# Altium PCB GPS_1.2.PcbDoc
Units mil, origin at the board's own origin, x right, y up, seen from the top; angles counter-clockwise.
Board outline 1968.5 x 2139.68 mil, 4 copper layers (Top Layer, GND, VDD, Bottom Layer); 63 components, 51 nets, 275 pads, 131 vias.
Unrouted connection lines stored in the file: 5.
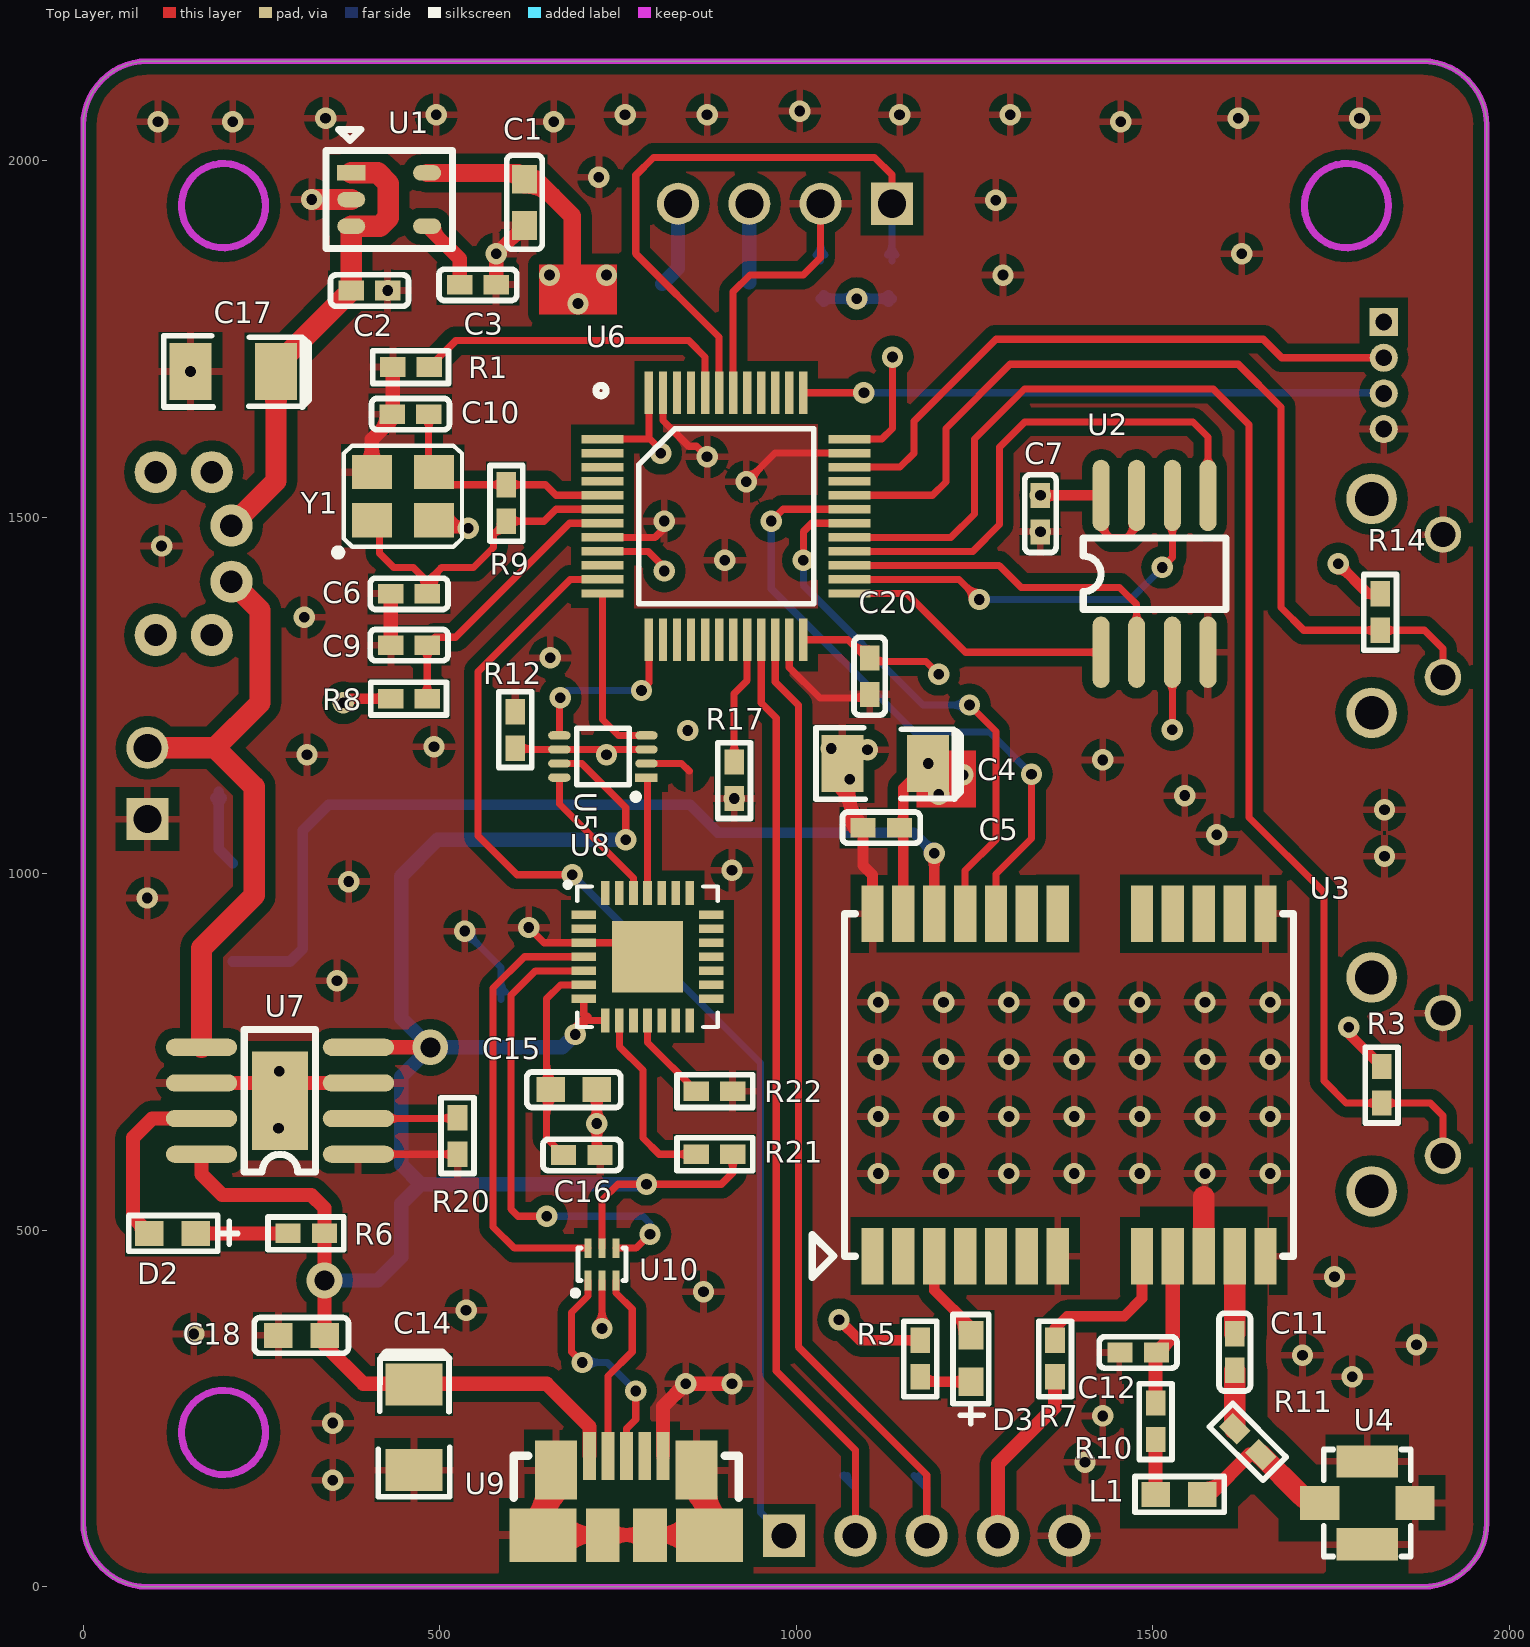
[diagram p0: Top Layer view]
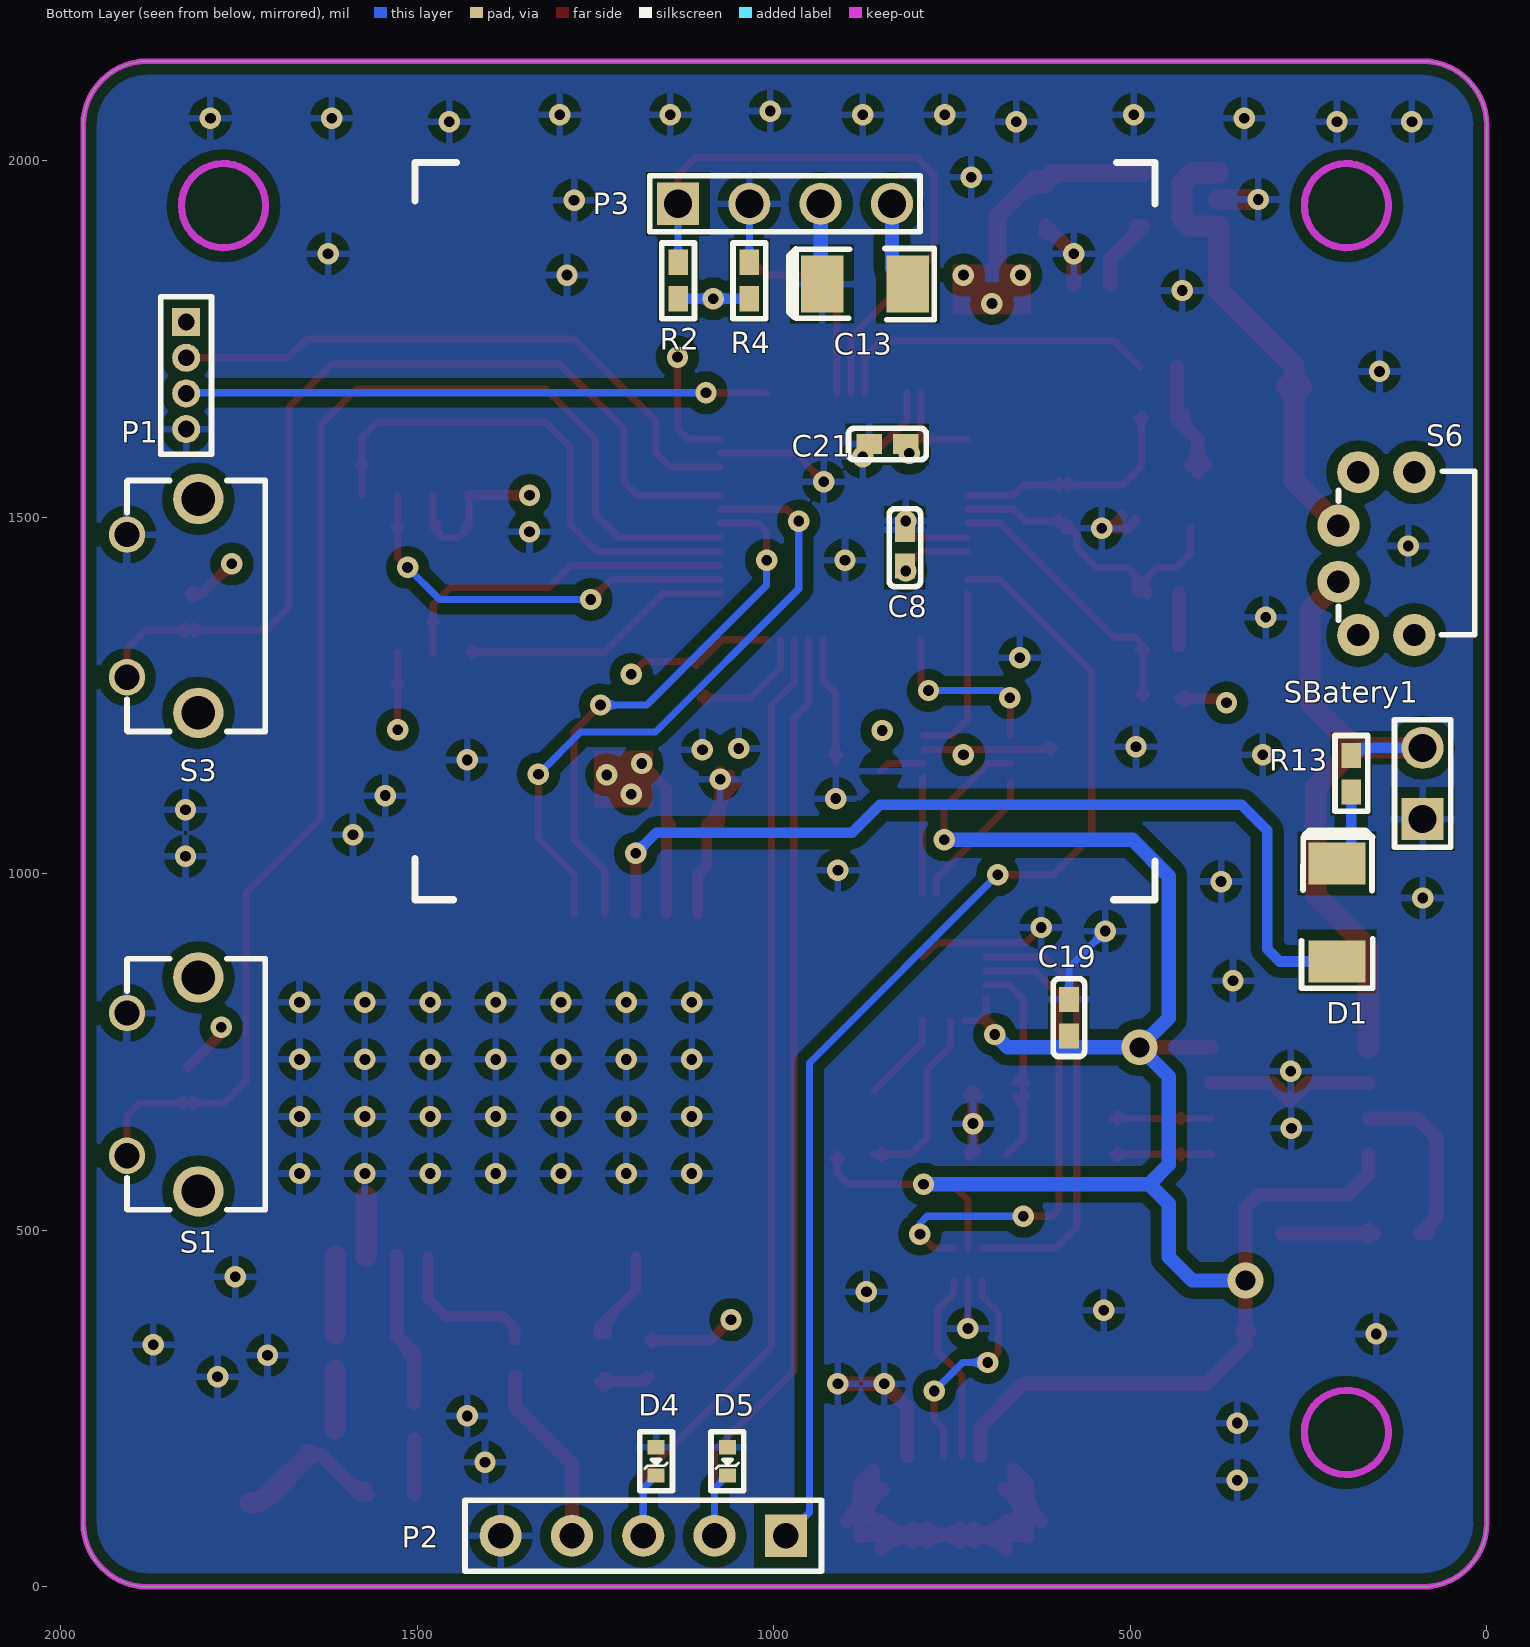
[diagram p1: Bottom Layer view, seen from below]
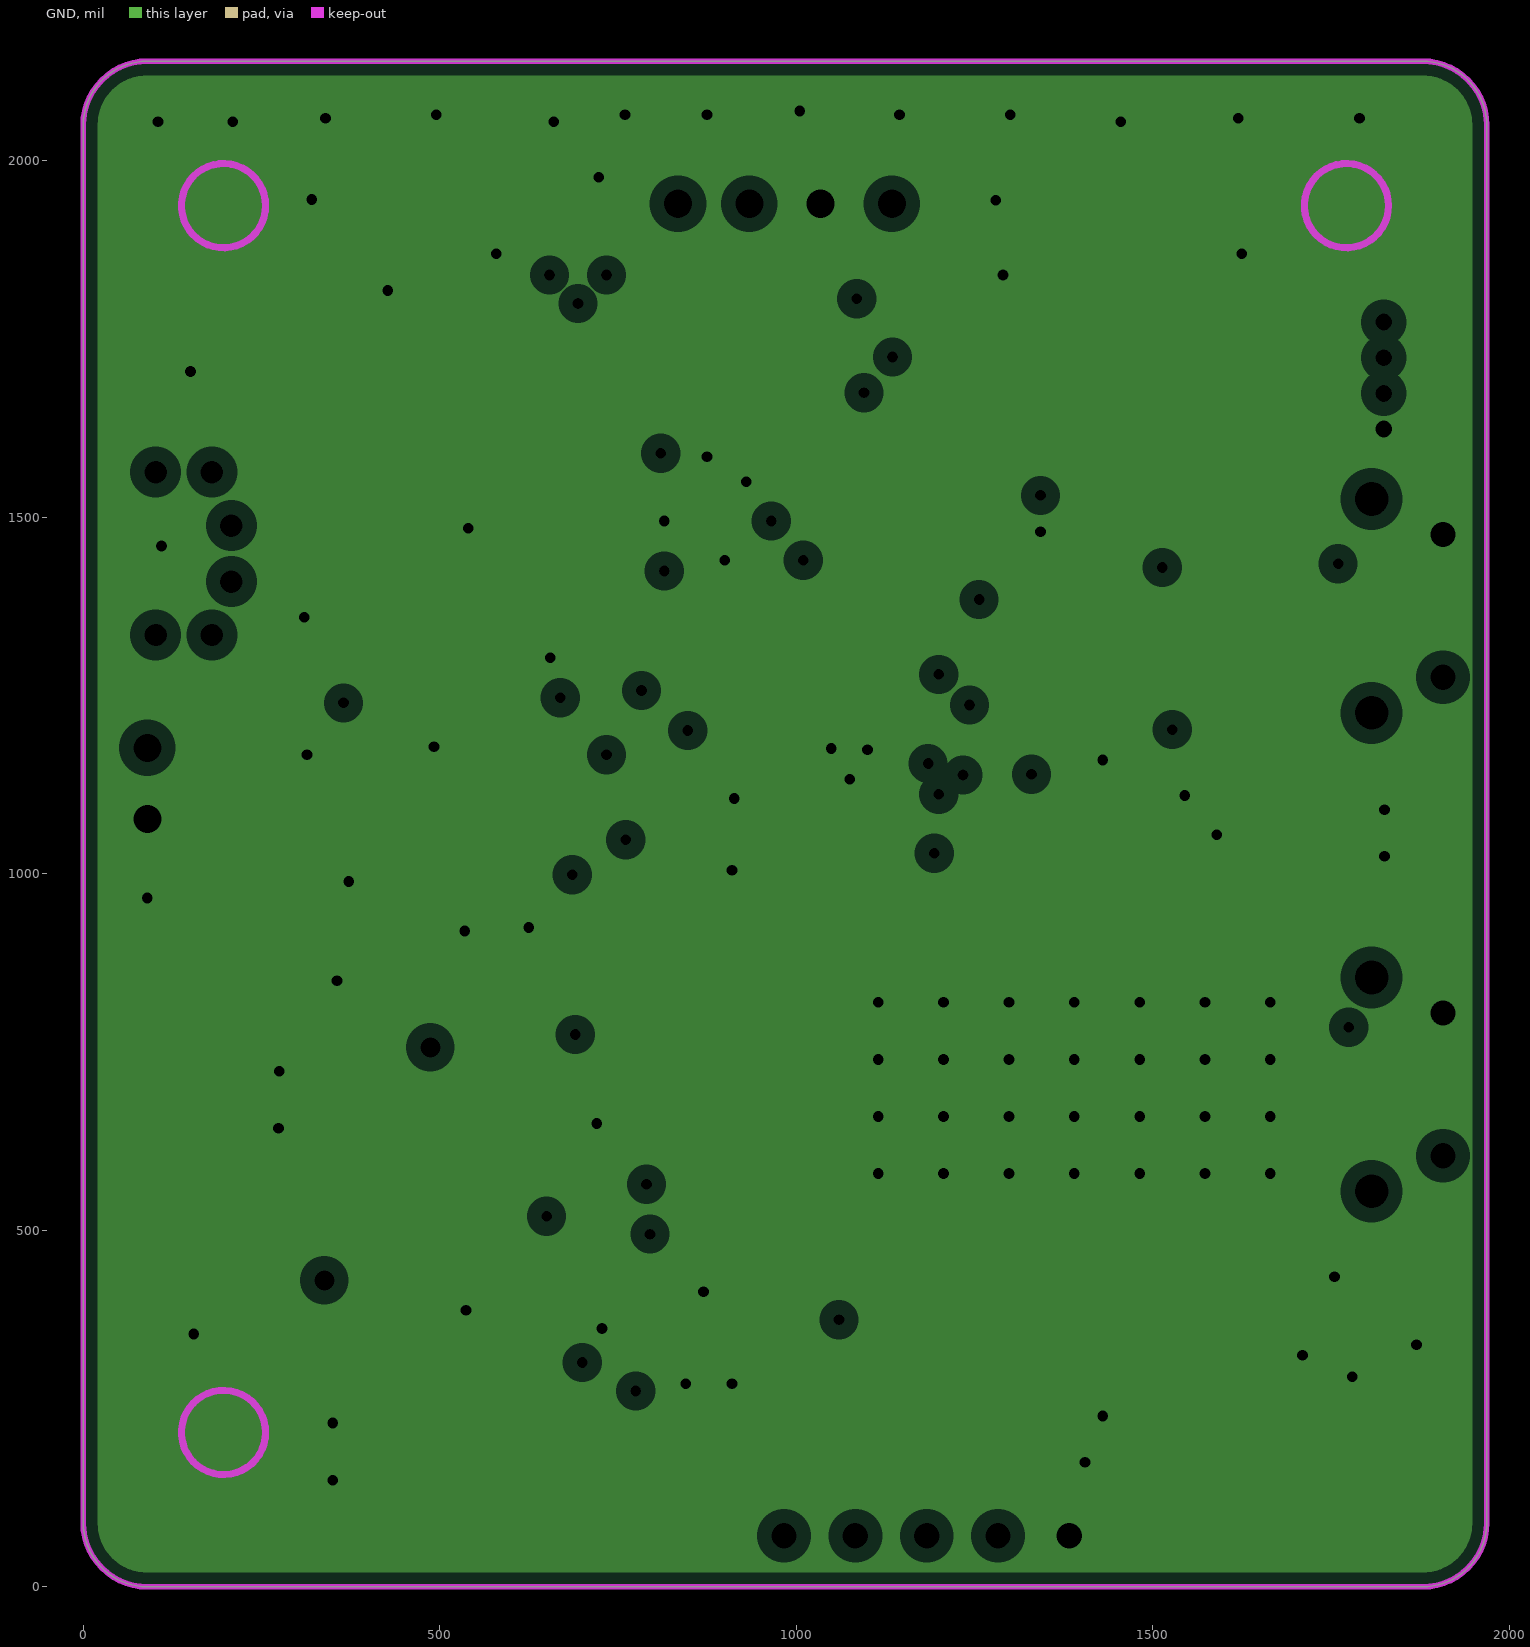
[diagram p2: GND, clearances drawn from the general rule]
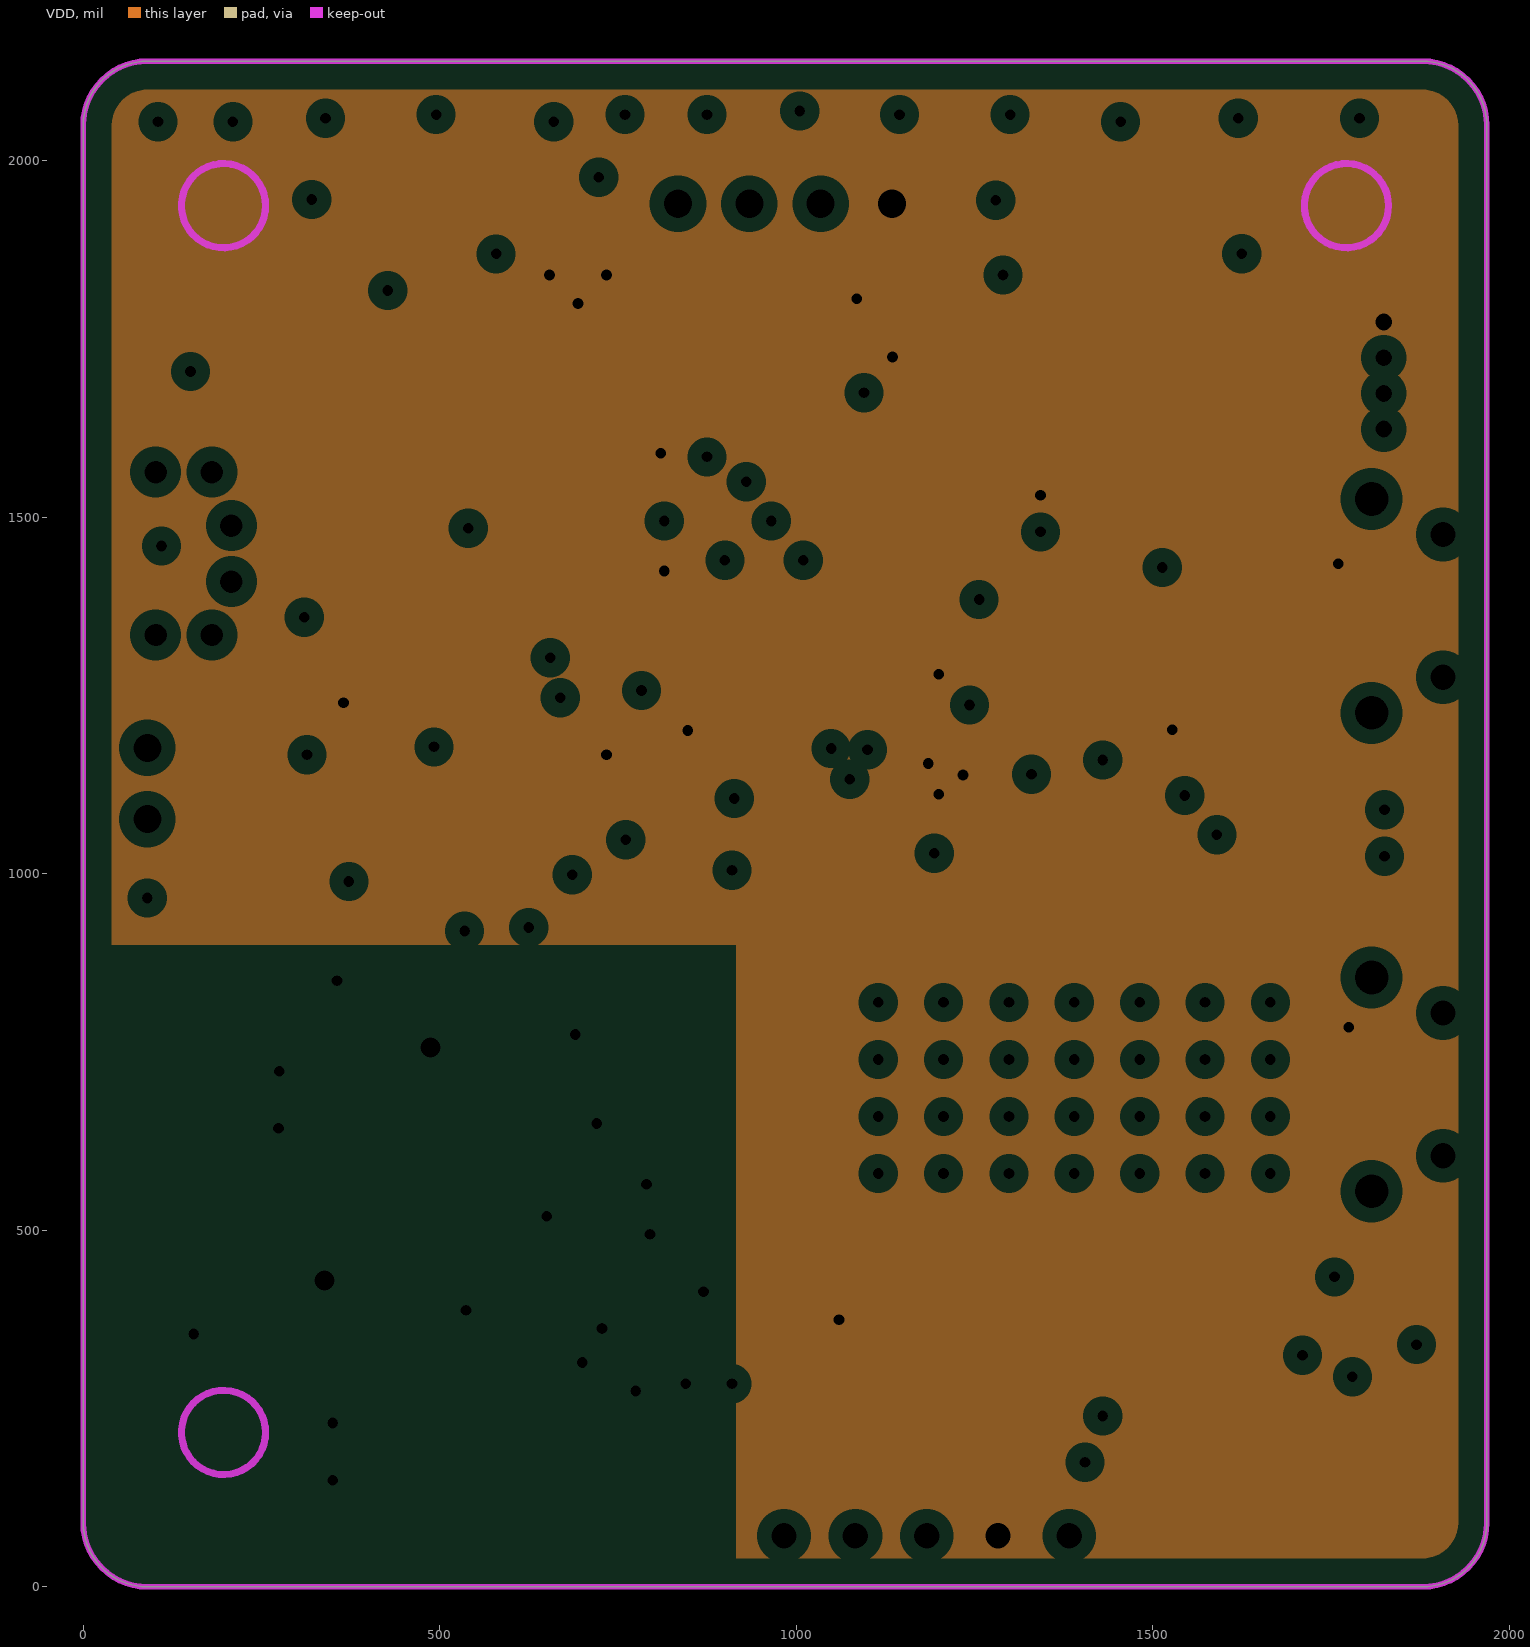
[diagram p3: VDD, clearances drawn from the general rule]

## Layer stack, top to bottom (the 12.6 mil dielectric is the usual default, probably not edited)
Top Layer: signal copper 1.4
Dielectric: core 12.6, FR-4, Dk 4.8
GND: plane copper 1.4, net GND
Dielectric: prepreg 12.6, FR-4, Dk 4.8
VDD: plane copper 1.4, net VDD
Dielectric: core 12.6, FR-4, Dk 4.8
Bottom Layer: signal copper 1.4

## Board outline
0,2049.68 0,90 ccw(c90,90) 90,0 1878.5,0 ccw(c1878.5,90) 1968.5,90 1968.5,2049.68 ccw(c1878.5,2049.68) 1878.5,2139.68 90,2139.68 ccw(c90,2049.68) 0,2049.68

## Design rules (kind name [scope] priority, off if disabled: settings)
Clearance Clearance_RF [InNetClass('RF')] p1: gap=30
Clearance [All] p2: gap=10
DiffPairsRouting [All] p1: maxlimit=10 minlimit=10 mostfreqgap=10 maxuncoupledlength=500
HoleSize [All] p1 off: absolutevalues=TRUE maxlimit=100 minlimit=1 maxpercent=80.000 minpercent=20.000
HoleToHoleClearance [All] p1 off: gap=10 allowstackedmicrovias=TRUE
LayerPairs [All] p1 off: enforce=TRUE
MinimumSolderMaskSliver [All] p1 off: minsoldermaskwidth=10
NetAntennae [All] p1 off: netantennaetolerance=0
PlaneClearance [All] p1: clearance=20
PlaneConnect [All] p1: planeconnectstyle=Relief reliefexpansion=20 reliefentries=4 reliefconductorwidth=10 reliefairgap=10
PolygonConnect [All] p1: connectstyle=Relief reliefconductorwidth=10 reliefentries=4 polygonreliefangle="90 Angle"
RoutingVias [All] p1: holewidth=28 width=50 viastyle="Through Hole" minholewidth=0 minwidth=0 maxholewidth=28 maxwidth=50
SilkToSilkClearance [All] p1 off: silktosilkclearance=10
SilkscreenOverComponentPads [All] p1 off: minsilkscreentomaskgap=10
SolderMaskExpansion [All] p1: expansion=4
Width [All] p1: maxlimit=50 minlimit=10 preferedwidth=10
18 further rules are at their usual default settings.

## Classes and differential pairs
net class RF: NetC11_1 NetL1_1 NetL1_2 RF_IN RF_VCC
differential pair D: +D_P -D_N

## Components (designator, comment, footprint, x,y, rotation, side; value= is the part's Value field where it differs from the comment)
C1 "10uF/10V" C0603 619,1941.68 r90 top
C2 "0.1uF/10V" C0402 376,1818 r180 top
C3 "0.01uF/10V" C0402 528,1826 r180 top
C4 "10uF/10V" 3528 1185,1154.68 r180 top
C5 "0.1uF/10V" C0402 1145,1064.68 r0 top
C6 "18pF/10V" C0402 431.5,1392.68 r180 top
C7 "0.01uF/10V" C0402 1342.5,1530.68 r90 top
C8 "0.01uF/10V" C0402 816,1431.68 r270 bottom
C9 "0.01uF/10V" C0402 431.5,1320.68 r180 top
C10 "18pF/10V" C0402 433.5,1644.68 r180 top
C11 "470pF" C0402 1615,303.68 r270 top
C12 "33nF" C0402 1454,328.68 r180 top
C13 "10uF/10V" C1206 872,1827 r180 bottom
C14 "10uF/10V" 3528 464,283.68 r270 top
C15 "4.7uF/10V" C0603 688,697.18 r180 top
C16 "0.1uF/10V" C0402 673.82,605.68 r180 top
C17 "10uF/10V" 3528 270.49,1704.53 r180 top
C18 "10uF/10V" C0603 306,352.68 r180 top
C19 "0.1uF/10V" C0402 586,772.68 r270 bottom
C20 "0.01uF/10V" C0402 1103,1302.68 r90 top
C21 "0.01uF/10V" C0402 815,1602.68 r180 bottom
D1 "IN4148" L1206 210,1014.68 r270 bottom
D2 "LED0" LED0603 158,495.68 r180 top
D3 "LED0" LED0603 1245,287.68 r90 top
D4 "PESD0402-140" 0402-TVS 1167,143.68 r270 bottom
D5 "PESD0402-140" 0402-TVS 1067,143.68 r270 bottom
L1 "6.8nH" R0603 1537,129.68 r180 top
P1 "MHDR1X4" SIP4_1.27 1824,1773.68 r0 bottom
P2 "Header 5" HDR1X5 983,71.68 r0 bottom
P3 "MHDR1X4" OLED 984.25,1939.68 r180 bottom locked
R1 "10K/5%" R0402 485.5,1710.68 r0 top
R2 "5.1K/5%" R0402 1134,1857.68 r90 bottom
R3 "10K/5%" R0402 1821,729.68 r90 top
R4 "5.1K/5%" R0402 1034.25,1857.68 r90 bottom
R5 "510R/5%" R0402 1174,345.68 r90 top
R6 "1K/5%" R0402 338.46,495.68 r0 top
R7 "10K/5%" R0402 1363,345.68 r90 top
R8 "10K/5%" R0402 482.5,1245.68 r0 top
R9 "1M/5%" R0402 593.5,1545.68 r90 top
R10 "10R/5%" R0402 1504,257.68 r90 top
R11 "0R/5%" R0402 1615,221.68 r135 top
R12 "10K/5%" R0402 606,1176 r270 top
R13 "105K/5%" R0402 190,1114.68 r270 bottom
R14 "10K/5%" R0402 1819,1392.68 r90 top
R17 "10K/5%" R0402 913,1156.68 r90 top
R20 "2K/5%" R0402 525,606.68 r270 top
R21 "1K/5%" R0402 859.82,606.68 r180 top
R22 "10K/5%" R0402 859.82,695.18 r180 top
S1 "SW-PB" KEY2 1907,704.68 r270 bottom
S3 "SW-PB" KEY2 1907,1375.68 r270 bottom
S6 "SW-PB" KEY1 208,1488.43 r270 bottom
SBatery1 "SBatery" SIP2 90,1076.68 r90 bottom
U1 "TPS73633DBVR" SOP5-TPS73633DBVR 376,1983 r0 top
U2 "FM25V01" SO-8 1427.5,1310.68 r90 top
U3 "NEO-M8N" NEO-M8N 1107,463.68 r0 top
U4 "antenna" "Active antenna" 1801,117.68 r180 top
U5 "TXS0102" R-PDSO-G8 790,1135 r180 top
U6 "STM32F10xC8T6" LQFP-48 728.5,1609.68 r0 top
U7 "TP4056" SO-8-1 276,681.68 r180 top
U8 "CP2102" QFN-28 702,942.68 r0 top
U9 "USB" MOLEX-47346-0001 710,183.68 r0 top
U10 "NUF2042XV6T1" UDFN 708,429.68 r0 top
Y1 "16MHz" OSCILLATOR-3.2X2.5 448.5,1529.68 r90 top

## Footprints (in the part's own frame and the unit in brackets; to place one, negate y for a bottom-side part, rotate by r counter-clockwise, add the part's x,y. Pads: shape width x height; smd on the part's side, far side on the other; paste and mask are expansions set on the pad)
0402-TVS [mil]
  rect 20x24 smd: 1(-52,2) 2(-12.31,2)
  silkscreen extent -74,-21 9,25
3528 [mil]
  rect 59.05x80 smd: 1(0,0) 2(120,0)
  silkscreen extent -46,-50 157,50
"Active antenna" [mm]
  rect 1.4x1.2 smd: 0(-1.7,0) 1(1.7,0)
  rect 2.2x1.15 smd: 0(0,1.475) 0(0,-1.475)
  silkscreen extent -1.55,-1.91 1.55,1.91
C0402 [mm]
  rect 0.9x0.7 smd: 1(0,0) 2(-1.3,0)
  silkscreen extent -2.04,-0.56 0.74,0.56
C0603 [mil]
  rect 40x35 smd: 1(-32.5,0) 2(32.5,0)
  silkscreen extent -66,-25 66,25
C1206 [mil]
  rect 59.05x80 smd: 1(-60,0) 2(60,0)
  silkscreen extent -106,-50 97,50
HDR1X5 [mm] "Connector; Header; 5 Position"
  rect 1.5x1.5 hole 0.9: 1(0,0)
  round 1.5 hole 0.9: 2(2.54,0) 3(5.08,0) 4(7.62,0) 5(10.16,0)
  silkscreen extent -1.27,-1.27 11.43,1.27
KEY1 [mm]
  round 1.5 hole 0.8: 0(-1.9,0.7) 0(-1.9,2.7) 0(3.9,0.7) 0(3.9,2.7) 1(0,0) 2(2,0)
  silkscreen extent -1.93,0 3.89,4.85
KEY2 [mm]
  round 1.8 hole 1.2: 0(-3.81,2.54) 0(3.81,2.54)
  round 1.3 hole 0.9: 1(-2.54,0) 2(2.54,0)
  silkscreen extent -4.47,0 4.47,4.93
L1206 [mm]
  rect 1.5x2.032 smd: 1(0,0) 2(3.5,0)
  silkscreen extent -1.16,-1.27 4.45,1.27
LED0603 [mil]
  rect 40x35 smd: 1(0,0) 2(65,0)
  silkscreen extent -59,-25 94,25
LQFP-48 [mm]
  rect 1.5x0.3 smd: 1(0,0) 2(0,-0.5) 3(0,-1) 4(0,-1.5) 5(0,-2) 6(0,-2.5) 7(0,-3) 8(0,-3.5) 9(0,-4) 10(0,-4.5) 11(0,-5) 12(0,-5.5) 25(8.8,-5.5) 26(8.8,-5) 27(8.8,-4.5) 28(8.8,-4) 29(8.8,-3.5) 30(8.8,-3) 31(8.8,-2.5) 32(8.8,-2) 33(8.8,-1.5) 34(8.8,-1) 35(8.8,-0.5) 36(8.8,0)
  rect 0.3x1.5 smd: 13(1.65,-7.15) 14(2.15,-7.15) 15(2.65,-7.15) 16(3.15,-7.15) 17(3.65,-7.15) 18(4.15,-7.15) 19(4.65,-7.15) 20(5.15,-7.15) 21(5.65,-7.15) 22(6.15,-7.15) 23(6.65,-7.15) 24(7.15,-7.15) 37(7.15,1.65) 38(6.65,1.65) 39(6.15,1.65) 40(5.65,1.65) 41(5.15,1.65) 42(4.65,1.65) 43(4.15,1.65) 44(3.65,1.65) 45(3.15,1.65) 46(2.65,1.65) 47(2.15,1.65) 48(1.65,1.65)
  silkscreen extent -0.24,-5.86 7.51,1.91
MOLEX-47346-0001 [mil]
  rect 18x67 smd: 1(0,0) 2(26,0) 3(52,0) 4(77.59,0) 5(103.18,0)
  rect 94x75 smd: 6(-65,-111) 9(168.14,-111)
  rect 59x83 smd: 7(-47,-20) 8(150.43,-20)
  rect 47x75 smd: 10(84.97,-111) 11(19,-111)
  silkscreen extent -106,-59 209,0
NEO-M8N [mm]
  rect 0.8x2 smd: 1(0,0) 2(1.1,0) 3(2.2,0) 4(3.3,0) 5(4.4,0) 6(5.5,0) 7(6.6,0) 8(9.6,0) 9(10.7,0) 10(11.8,0) 11(12.9,0) 12(14,0) 13(14,12.2) 14(12.9,12.2) 15(11.8,12.2) 16(10.7,12.2) 17(9.6,12.2) 18(6.6,12.2) 19(5.5,12.2) 20(4.4,12.2) 21(3.3,12.2) 22(2.2,12.2) 23(1.1,12.2) 24(0,12.2)
  silkscreen extent -2.14,-0.76 15,12.2
OLED [mm]
  rect 1.5x1.5 hole 1: 1(-3.81,0)
  round 1.5 hole 1: 2(-1.27,0) 3(1.27,0) 4(3.81,0)
  silkscreen extent -13.18,-24.79 13.18,1.47
OSCILLATOR-3.2X2.5 [mil]
  rect 48x56 smd: 1(-33.73,43.65) 2(-33.73,-43.65) 3(33.73,-43.65) 4(33.73,43.65)
  silkscreen extent -83,-83 71,95
QFN-28 [mil]
  rect 34x12 smd mask+5: 1(0,0) 2(0,-19.68) 3(0,-39.37) 4(0,-59.06) 5(0,-78.74) 6(0,-98.43) 7(0,-118.11) 15(179,-118.11) 16(179,-98.43) 17(179,-78.74) 18(179,-59.06) 19(179,-39.37) 20(179,-19.68) 21(179,0)
  rect 12x34 smd mask+5: 8(30.44,-148.56) 9(50.13,-148.56) 10(69.81,-148.56) 11(89.5,-148.56) 12(109.19,-148.56) 13(128.87,-148.56) 14(148.56,-148.56) 22(148.56,30.44) 23(128.87,30.44) 24(109.19,30.44) 25(89.5,30.44) 26(69.82,30.44) 27(50.13,30.44) 28(30.44,30.44)
  rect 100x100 smd mask+5: 29(89.5,-59.06)
  silkscreen extent -25,-158 188,44
R0402 [mm]
  rect 0.9x0.7 smd: 1(0,0) 2(-1.3,0)
  silkscreen extent -2.01,-0.58 0.69,0.58
R0603 [mil]
  rect 40x35 smd: 1(-32.5,0) 2(32.5,0)
  silkscreen extent -63,-25 62,25
R-PDSO-G8 [mm]
  rect 0.8x0.3 smd: 1(0,0)
  oval 0.8x0.3 smd: 2(0,-0.5) 3(0,-1) 4(0,-1.5) 5(3.1,-1.5) 6(3.1,-1) 7(3.1,-0.5) 8(3.1,0)
  silkscreen extent 0.29,-1.75 2.49,0.78
SIP2 [mm]
  rect 1.5x1.5 hole 1: 1(0,0)
  round 1.5 hole 1: 2(2.54,0)
  silkscreen extent -1,-1 3.54,1
SIP4_1.27 [mm]
  rect 1x1 hole 0.6: 1(0,0)
  round 1 hole 0.6: 2(0,1.27) 3(0,2.54) 4(0,3.81)
  silkscreen extent -0.9,-0.9 0.9,4.71
SO-8 [mil]
  oval 100x24 smd: 1(0,0) 2(0,-50) 3(0,-100) 4(0,-150) 5(220,-150) 6(220,-100) 7(220,-50) 8(220,0)
  silkscreen extent 60,-175 160,25
SO-8-1 [mil]
  rect 78.74x137.8 smd: 0(0,0)
  oval 100x24 smd: 1(-110,75) 2(-110,25) 3(-110,-25) 4(-110,-75) 5(110,-75) 6(110,-25) 7(110,25) 8(110,75)
  silkscreen extent -50,-100 50,100
SOP5-TPS73633DBVR [mm]
  rect 1x0.55 smd: 1(0,0)
  oval 1x0.55 smd: 2(0,-0.95) 3(0,-1.9) 4(2.7,-1.9) 5(2.7,0)
  silkscreen extent -0.9,-2.7 3.6,1.55
UDFN [mm]
  rect 0.25x0.7 smd: 1(0,0) 2(0.5,0) 3(1,0) 4(1,1.15) 5(0.5,1.15) 6(0,1.15)
  silkscreen extent -0.55,-0.55 1.35,1.15

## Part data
C1 C2 C3 C4 C5 C6 C7 C8 C9 C10 C11 C12 C15 C16 C18 C19 C20 C21: library part Cap, "Capacitor"
C13 C14 C17: library part "Cap Pol2", "Polarized Capacitor (Axial)"
D1: library part ZENER2, "Zener Diode"
D2 D3: "Typical INFRARED GaAs LED"
D4 D5: library part "D Zener", "Zener Diode"
L1: library part Inductor, "Inductor"
P1 P3: "Header, 4-Pin"
P2: "Header, 5-Pin"
R1 R2 R3 R4 R5 R6 R7 R8 R9 R10 R11 R12 R13 R14 R17 R20: library part Res2, "Resistor"
R21 R22: library part Resistor, "Resistor SMD - IEC symbol version"
S1 S3 S6: "Switch"
U2: library part FM25CL64B
U6: library part STM32F100C8T6
U8: "Imported"
U9: library part MICRO_USB
Y1: library part XTAL3

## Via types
v1: diameter 30, hole 15, Top Layer to Bottom Layer, 129 vias
v2: diameter 50, hole 28, Top Layer to Bottom Layer, 2 vias

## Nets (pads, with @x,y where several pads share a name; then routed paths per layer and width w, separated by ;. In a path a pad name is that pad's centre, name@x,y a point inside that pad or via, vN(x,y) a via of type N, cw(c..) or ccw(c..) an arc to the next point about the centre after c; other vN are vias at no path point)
BAT: R13.2 S6.2 SBatery1.2 U7.5 | length 979
  Top Layer w30: SBatery1.2 185,1176.68 ; U7.5 166,895.68 240,969.68 240,1121.87 ; S6.2 248,1369.68 248,1239.68 185,1176.68 ; 239.91,1121.78 185,1176.68
  Bottom Layer w15: SBatery1.2 179.18,1176.68 R13.2 ; 158.23,1176.68 cw(c158.23,1138.03) R13.2@185.56,1165.36
D_N: U8.5 U10.4 | length 690.3
  Top Layer w10: v1(650,519.68) 610,519.68 600,529.68 600,829.68 634.26,863.94 U8.5 ; U10.4 775.28,474.96 v1(795,494.68)
  Bottom Layer w10: v1(650,519.68) 785,519.68 795,509.68 v1(795,494.68)
D_P: U8.4 U10.6 | length 625.5
  Top Layer w10: U8.4 618.94,883.63 575,839.68 575,504.68 604.72,474.96 U10.6
FRAM_CLK: U2.6 U6.26 | length 640.1
  Top Layer w10: U6.26 1228.35,1412.84 v1(1256.5,1384.68) ; v1@1246.5,1384.68 ccw(c1222.36,1384.68) 1239.43,1401.76 ccw(c1256.5,1418.83) v1@1256.5,1394.68 ; v1(1513.5,1429.68) 1527.5,1443.69 U2.6 ; U2.6@1522.55,1487.74 cw(c1510.6,1475.79) 1527.5,1475.79 cw(c1544.4,1475.79) U2.6@1532.45,1487.74
  Bottom Layer w10: v1(1256.5,1384.68) 1468.5,1384.68 v1(1513.5,1429.68)
FRAM_CS: U2.1 U6.25 | length 413.2
  Top Layer w10: U6.25 1155.04,1393.15 1237.5,1310.68 U2.1 ; U2.1@1422.55,1305.74 ccw(c1410.6,1293.79) 1410.6,1310.68 ccw(c1410.6,1327.58) U2.1@1422.55,1315.63
FRAM_MISO: U2.2 U6.27 | length 518.8
  Top Layer w10: U6.27 1284.67,1432.52 1315.5,1401.68 1453.5,1401.68 1477.5,1377.68 U2.2 ; U2.2@1472.55,1353.63 ccw(c1460.6,1365.58) 1477.5,1365.58 ccw(c1494.4,1365.58) U2.2@1482.45,1353.63
FRAM_MOSI: U2.5 U6.28 | length 758.5
  Top Layer w10: U6.28 1247.52,1452.2 1285,1489.68 1285,1598.18 1320.5,1633.68 1556.5,1633.68 1577.5,1612.68 U2.5 ; U2.5@1572.55,1573.63 ccw(c1560.6,1585.58) 1577.5,1585.58 ccw(c1594.4,1585.58) U2.5@1582.45,1573.63
GND: C1.1 C2.2 C3.2 C4.2 C5.2 C6.1 C7.2 C8.2 C9.1 C10.1 C12.1 C13.1 C14.2 C15.1 C16.2 C17.2 C18.2 C19.2 C20.2 C21.2 D4.1 D5.1 P1.4 P2.5 P3.2 R1.2 R12.2 R17.2 R20.1 R22.2 S1.1 S3.1 SBatery1.1 U1.2 U2.4 U3.7 U3.10 U3.12 U3.13 U3.24 U4.0 U5.2 U6.8 U6.23 U6.35 U6.47 U7.1 U7.3 U7.6 U8.3 U8.29 U9.5 U9.6 U9.7 U9.8 U9.9 U9.10 U9.11 U10.2 Y1.2 Y1.4 | length 4510.8
  Top Layer w10: U7.1 R20.1 ; U7.1@428.95,601.74 cw(c440.9,589.79) 440.9,606.68 cw(c440.9,623.58) U7.1@428.95,611.63 ; R20.1@518.79,600.48 ccw(c503.8,585.49) 503.8,606.68 ccw(c503.8,627.88) R20.1@518.79,612.89 ; v1(625,924.68) 646.37,903.31 U8.3 771.81,903.31 U8.29 ; v1@720.61,369.44 ccw(c703.54,386.51) 727.69,386.51 ccw(c751.83,386.51) v1@734.76,369.44 ; v1(727.69,362.37) U10.2 ; U6.8 802.2,1471.89 815,1484.68 v1(815,1494.68) ; U5.2 839.31,1154.68 850,1144 ; U6.47 813.15,1635.85 849.31,1599.68 860,1599.68 v1(875,1584.68) ; v1(930,1549.68) 970.31,1590 U6.35 ; v1@930,1559.68 ccw(c930,1583.83) 947.07,1566.76 ccw(c964.14,1549.68) v1@940,1549.68 ; U6.23 990.31,1289.37 1033.18,1246.5 C20.2@1103,1246.5 ; 1079.24,1246.5 ccw(c1079.24,1271.33) C20.2@1096.79,1253.77 ; 1084.37,1246.5 cw(c1084.37,1228.94) C20.2@1096.79,1241.36
  Top Layer w15: Y1.2 503.43,1484.68 v1(540,1484.68) cw(c540,1516.68) Y1.2@511.07,1503 ; C15.1@713.43,690.11 cw(c696.36,673.04) 720.5,673.04 cw(c744.64,673.04) C15.1@727.57,690.11 ; v1@715.2,644.38 cw(c702.39,631.58) 720.5,631.58 cw(c738.61,631.58) v1@725.8,644.38 ; v1@715.2,654.99 ccw(c702.39,667.79) 720.5,667.79 ccw(c738.61,667.79) v1@725.8,654.99 ; C16.2@716.62,610.13 ccw(c707.26,619.49) 720.5,619.49 ; 720.5,622.2 ccw(c737.58,622.2) C16.2@725.5,610.13 ; C15.1 720.5,610.18 C16.2 ; C4.2@1052.46,1126.1 cw(c1021.98,1082.11) 1075.5,1082.11 ; C4.2@1061,1138.44 cw(c1041.82,1110.75) 1075.5,1110.75 ; C4.2@1069.7,1127.38 cw(c1055.69,1113.37) 1075.5,1113.37 ; 1075.5,1078.35 ccw(c1103.55,1078.35) C5.2@1083.72,1058.52 ; 1075.5,1114.57 ccw(c1139.76,1114.57) C5.2@1094.32,1069.13 ; C4.2@1075.5,1115.79 cw(c1091.9,1115.79) C4.2@1080.3,1127.38 ; C4.2@1075.5,1116.38 cw(c1092.83,1116.38) C4.2@1080.58,1128.64 ; C4.2@1075.5,1144.68 1075.5,1083 C5.2 1093.82,1011.55 1107,998.37 U3.24 ; 1076.38,1082.13 cw(c1058.94,1064.68) C5.2@1083.6,1064.68 ; C5.2@1089.38,1060.24 cw(c1078.66,1049.52) 1093.82,1049.52 cw(c1108.98,1049.52) C5.2@1098.26,1060.24
  Top Layer w20: U7.6 251,706.68 276,681.68 301,706.68 U7.3 ; Y1.4@394.95,1573.32 ccw(c371.05,1597.22) 404.85,1597.22 ccw(c438.65,1597.22) Y1.4@414.75,1573.32 ; Y1.4 404.85,1609.03 434.32,1638.5 R1.2 ; 415.38,1619.56 ccw(c390.26,1644.68) C10.1@425.79,1644.68 ; C9.1 C6.1 ; C3.2 v1(579.18,1869.37) C1.1 ; C1.1@601.93,1892.11 cw(c619,1875.04) C1.1@619,1899.18 ; U9.6@625.55,92.13 ccw(c578.61,139.08) 645,139.08 ccw(c711.39,139.08) U9.6@664.45,92.13 ; U9.6@645,70.66 cw(c731.77,70.66) U9.7@675.62,136.82 ; 645,113.88 cw(c695.09,113.88) U9.7@662.68,152.07 ; U9.7 645,145.68 U9.6 U9.11 U9.10 U9.9 878.14,145.97 U9.8 ; U9.6@673.95,53.24 cw(c720.89,6.29) 720.89,72.68 cw(c720.89,139.08) U9.6@673.95,92.13 ; U9.11@719.45,63.14 ccw(c696.41,40.09) 696.41,72.68 ccw(c696.41,105.28) U9.11@719.45,82.23 ; U9.11@738.55,63.14 cw(c761.59,40.09) 761.59,72.68 cw(c761.59,105.28) U9.11@738.55,82.23 ; U9.10@785.43,63.14 ccw(c762.38,40.09) 762.38,72.68 ccw(c762.38,105.28) U9.10@785.43,82.23 ; U9.10@804.52,63.14 cw(c827.56,40.09) 827.56,72.68 cw(c827.56,105.28) U9.10@804.52,82.23 ; U9.5 813.18,252.87 v1(845,284.68) v1(910,284.68) ; U9.8@847.73,136.88 cw(c790.98,70.73) U9.9@878.14,70.73 ; U9.9@849.2,53.24 ccw(c802.25,6.29) 802.25,72.68 ccw(c802.25,139.08) U9.9@849.2,92.13 ; U9.9@858.7,92.13 ccw(c811.75,139.08) 878.14,139.08 ccw(c944.53,139.08) U9.9@897.59,92.13 ; U9.8@860.75,152.06 cw(c828.3,114.23) 878.14,114.23
  Top Layer w30: v1(320.6,1945.6) U1.2 ; U3.10 1571.57,546.85
  Bottom Layer w10: v1@535,909.68 cw(c535,885.54) 552.07,902.61 cw(c569.14,919.68) v1@545,919.68 ; v1(535,919.68) 586,868.69 C19.2 ; C19.2@579.79,834.01 ccw(c564.8,849) 586,849 ccw(c607.2,849) C19.2@592.21,834.01
  Bottom Layer w20: C13.1@934.25,1829.25 934.25,1939.68
  other v1: 350,149.68 1405,174.68 350,229.68 1430,239.68 1780,294.68 1710,324.68 1870,339.68 155,354.68 537,388 870,414 1755,434.68 1115,579.68 1206.67,579.68 1298.33,579.68 1390,579.68 1481.67,579.68 1573.33,579.68 1665,579.68 274,643 720.5,649.68 1115,659.68 1206.67,659.68 1298.33,659.68 1390,659.68 1481.67,659.68 1573.33,659.68 1665,659.68 275,723 1115,739.68 1206.67,739.68 1298.33,739.68 1390,739.68 1481.67,739.68 1573.33,739.68 1665,739.68 1115,819.68 1206.67,819.68 1298.33,819.68 1390,819.68 1481.67,819.68 1573.33,819.68 1665,819.68 356,850 90,966 372.65,989.11 910,1005 1825,1024.68 1590,1054.68 1825,1089.68 913,1105.5 1545,1109.68 1075,1132.68 1430,1159.68 314,1167.04 1100,1174 1049,1175.68 492,1178 655,1303 310,1359.68 900,1439.68 110,1459.68 1342.5,1479.5 150.49,1704.53 427.18,1818 1290,1839.68 1625,1869.68 1280,1944.68 723,1977 105,2054.68 210,2054.68 660,2054.68 1455,2054.68 340,2059.68 1620,2059.68 1790,2059.68 495,2064.68 760,2064.68 875,2064.68 1145,2064.68 1300,2064.68 1005,2069.68
KEY0: R3.2 S1.2 U6.29 | length 2001.7
  Top Layer w10: U6.29 1217.2,1471.89 1250,1504.68 1250,1609.68 1320,1679.68 1585,1679.68 1635,1629.68 1635,1079 1740,974 1740,709.68 1771.18,678.5 R3.2 1889.18,678.5 1907,660.68 S1.2 ; R3.2@1814.79,672.3 ccw(c1799.8,657.31) 1799.8,678.5 ccw(c1799.8,699.7) R3.2@1814.79,684.71 ; R3.2@1827.21,672.3 cw(c1842.2,657.31) 1842.2,678.5 cw(c1842.2,699.7) R3.2@1827.21,684.71
KEY1: U6.33
KEY2: R14.2 S3.2 U6.32 | length 1388.8
  Top Layer w10: U6.32 1191.26,1530.95 1210,1549.68 1210,1624.68 1300,1714.68 1620,1714.68 1680,1654.68 1680,1373.32 1711.82,1341.5 R14.2 1881.18,1341.5 1907,1315.68 S3.2 ; R14.2@1812.79,1335.3 ccw(c1797.8,1320.31) 1797.8,1341.5 ccw(c1797.8,1362.7) R14.2@1812.79,1347.71 ; R14.2@1825.21,1335.3 cw(c1840.2,1320.31) 1840.2,1341.5 cw(c1840.2,1362.7) R14.2@1825.21,1347.71
NetC2_1: C2.1 C17.1 S6.1 U1.1 U1.3 | length 707.6
  Top Layer w30: S6.1 270.49,1550.91 270.49,1712.49 C2.1 376,1848 U1.3 416.2,1908.2 428,1920 428,1968 413,1983 U1.1 ; C17.1@260.22,1683.78 cw(c235.42,1658.98) 270.49,1658.98 cw(c305.56,1658.98) C17.1@280.76,1683.78
NetC3_1: C3.1 U1.4 | length 119.5
  Top Layer w20: U1.4 528,1862.5 C3.1 ; U1.4@491.98,1908.2 ccw(c515.37,1908.2) 498.83,1891.66
NetC11_1: C11.1 R11.1 | length 82
  Top Layer w30: R11.1 C11.1
NetC15_2: C15.2 C16.1 U8.6 | length 383.8
  Top Layer w10: C15.2@644.16,688.35 cw(c630.06,674.25) 650,674.25 ; C15.2@644.16,706.02 ccw(c630.06,720.12) 650,720.12 ; 650,659.76 cw(c690.42,659.76) C15.2@661.84,688.35 ; 650,734.61 ccw(c690.42,734.61) C15.2@661.84,706.02 ; C16.1 650,629.5 650,824.68 669.57,844.26 U8.6
NetD1_1: D1.1 R13.1 | length 132.1
  Bottom Layer w15: R13.1@185.56,1106.31 cw(c174.84,1095.59) 190,1095.59 cw(c205.16,1095.59) R13.1@194.44,1106.31 ; R13.1 190,1034.68 D1.1
NetD1_2: D1.2 U3.22 | length 1341.6
  Top Layer w15: v1@1188.31,1023.38 cw(c1175.51,1010.58) 1193.61,1010.58 cw(c1211.72,1010.58) v1@1198.92,1023.38 ; U3.22 v1(1193.61,1028.68)
  Bottom Layer w15: D1.2 290.2,876.89 308,894.68 308,1060.68 344,1096.68 851,1096.68 890.19,1057.49 1164.81,1057.49 v1(1193.61,1028.68) ; v1@1186.11,1028.68 ccw(c1168.01,1028.68) 1180.81,1041.49 ccw(c1193.61,1054.29) v1@1193.61,1036.18
NetD2_1: D2.1 R6.2 | length 157.7
  Top Layer w20: D2.1 R6.2 ; D2.1@165.8,490.38 cw(c178.61,477.58) 178.61,495.68 cw(c178.61,513.79) D2.1@165.8,500.99
NetD2_2: D2.2 U7.7 | length 269.7
  Top Layer w20: D2.2@75.93,512.76 cw(c58.86,495.68) D2.2@83,495.68 ; D2.2 70,518.69 70,629.68 97,656.68 U7.7
NetD3_1: D3.1 R5.2 | length 131.4
  Top Layer w15: R5.2 1180.82,287.68 D3.1 ; R5.2@1178.44,295.01 ccw(c1196.12,312.68) 1196.12,287.68 ; D3.1@1237.93,280.61 ccw(c1220.86,263.54) 1220.86,287.68 ccw(c1220.86,311.83) D3.1@1237.93,294.76
NetD3_2: D3.2 U3.3 | length 169.3
  Top Layer w15: U3.3 1193.61,416.07 1245,364.68 D3.2 ; 1221.21,388.47 cw(c1187.92,355.18) D3.2@1235,355.18
NetL1_1: L1.1 R11.2 U4.1 | length 243.6
  Top Layer w20: L1.1 1580,129.68 1635.81,185.49 R11.2 ; L1.1@1572,137.18 ccw(c1572,174.61) 1598.46,148.15
  Top Layer w30: R11.2 1708.34,128.34 ccw(c1734.07,154.07) U4.1
NetL1_2: L1.2 R10.2 | length 77
  Top Layer w20: R10.2 1504,130.18 L1.2
NetR1_1: R1.1 U6.44 | length 461.8
  Top Layer w10: R1.1 522.5,1747.68 849.5,1747.68 872.2,1724.98 U6.44
NetR7_1: R7.1 U3.8 | length 215.3
  Top Layer w15: R7.1 1363,362.68 1380,379.68 1459.91,379.68 1484.95,404.73 U3.8
NetR17_1: R17.1 U6.20 | length 212.4
  Top Layer w10: R17.1@906.79,1166.83 ccw(c891.8,1181.82) 913,1181.82 ccw(c934.2,1181.82) R17.1@919.21,1166.83 ; R17.1 913,1252.68 931.26,1270.94 U6.20
NetR20_2: R20.2 U7.2 | length 199.7
  Top Layer w10: U7.2 R20.2@525.82,656.68 ; U7.2@428.95,651.74 cw(c440.9,639.79) 440.9,656.68 cw(c440.9,673.58) U7.2@428.95,661.63 ; 500.95,656.68 ccw(c500.95,681.91) R20.2@518.79,664.07 ; 506.66,656.68 cw(c506.66,639.52) R20.2@518.79,651.66
NetR21_1: R21.1 U8.9 | length 295.7
  Top Layer w10: U8.9 752.13,757.56 785,724.68 785,629.68 808,606.68 R21.1 ; R21.1@849.67,600.48 ccw(c834.69,585.49) 834.69,606.68 ccw(c834.69,627.88) R21.1@849.67,612.89
NetR22_1: R22.1 U8.11 | length 127.2
  Top Layer w10: U8.11 791.5,763.5 R22.1
NetU9_2: U9.2 U10.3 | length 269.5
  Top Layer w10: U9.2 736,295.68 770,329.68 770,389.68 747.37,412.31 U10.3
NetU9_3: U9.3 U10.1 | length 356.6
  Top Layer w10: v1(700,314.68) 685,329.68 685,384.68 708,407.68 U10.1 ; U9.3 762,221.81 775,234.81 v1(775,274.68)
  Bottom Layer w10: v1(700,314.68) 735,314.68 v1(775,274.68) ; v1@707.07,307.61 cw(c724.14,290.54) 724.14,314.68 cw(c724.14,338.83) v1@707.07,321.76
NRST: C9.2 R8.1 U6.7 | length 458
  Top Layer w10: R8.1@476.3,1251.89 ccw(c461.31,1266.88) 482.5,1266.88 ccw(c503.7,1266.88) R8.1@488.71,1251.89 ; C9.2@476.48,1314.48 cw(c461.93,1299.93) 482.5,1299.93 ; R8.1 C9.2@482.5,1320.5 ; 482.5,1299.05 cw(c504.32,1299.05) C9.2@488.89,1314.48 ; C9.2 493.69,1331.68 522,1331.68 681.89,1491.57 U6.7
OSC_IN: C10.2 R9.1 U6.5 Y1.3 | length 433.7
  Top Layer w10: C10.2@478.48,1638.48 cw(c463.93,1623.93) 484.5,1623.93 ; 484.5,1623.05 cw(c506.32,1623.05) C10.2@490.89,1638.48 ; C10.2@484.5,1644.68 484.5,1571.85 510.67,1545.68 R9.1 648.5,1545.68 663.24,1530.95 U6.5 ; R9.1@587.3,1539.48 ccw(c572.31,1524.49) 572.31,1545.68 ccw(c572.31,1566.88) R9.1@587.3,1551.89 ; R9.1@599.71,1539.48 cw(c614.7,1524.49) 614.7,1545.68 cw(c614.7,1566.88) R9.1@599.71,1551.89
OSC_OUT: C6.2 R9.2 U6.6 Y1.1 | length 662.2
  Top Layer w10: Y1.1@415.85,1485.73 415.85,1449.34 435.5,1429.68 462.87,1429.68 482.69,1409.87 ; 467.91,1424.64 cw(c438.6,1395.32) C6.2@479.97,1392.61 ; C6.2@476.06,1388.89 cw(c492.71,1394.87) 480.2,1407.38 ; C6.2@477.54,1399.8 ccw(c470.27,1409.87) 482.69,1409.87 ; C6.2 482.69,1409.87 ; 483.51,1409.04 cw(c467.88,1393.4) C6.2@489.94,1391.95 ; C6.2@485.47,1392.27 cw(c509.12,1400.77) 491.35,1418.53 ; C6.2@487.83,1399.8 cw(c495.1,1409.87) 482.68,1409.87 ; C6.2@494.88,1395.65 cw(c525.53,1406.66) 502.5,1429.68 ; 573.54,1474.54 cw(c591.23,1456.84) R9.2@592.91,1481.81 ; R9.2@581.3,1482.3 ccw(c573.03,1490.57) R9.2@584.72,1490.57 ; R9.2@599.71,1488.3 cw(c614.7,1473.31) 614.7,1494.5 cw(c614.7,1515.7) R9.2@599.71,1500.71 ; U6.6 663.08,1511.26 646.32,1494.5 R9.2 575.5,1476.5 575.5,1457.68 547.5,1429.68 502.5,1429.68 ; 482.69,1409.87 502.5,1429.68
RF_IN: C11.2 U3.11 | length 108.8
  Top Layer w30: C11.2@1614.87,354.87 U3.11
RF_VCC: C12.2 R10.1 U3.9 | length 230.7
  Top Layer w20: R10.1 1504,327.5 C12.2 1528.26,351.76 U3.9 ; C12.2@1512.9,328.68 cw(c1531.53,328.68) C12.2@1518.35,341.86
RXD_G: U3.21 U6.30 | length 811.3
  Top Layer w10: v1(1010,1439.68) 1010,1479.68 1021.89,1491.57 U6.30 ; U3.21 1236.92,1004.68 1280,1047.76 1280,1199.68 v1(1243,1236.68)
  Bottom Layer w10: v1(1010,1439.68) 1010,1404.68 1178,1236.68 v1(1243,1236.68) ; v1@1235.93,1229.61 ccw(c1218.86,1212.54) 1218.86,1236.68 ccw(c1218.86,1260.83) v1@1235.93,1243.76
RXD_MCU: U5.5 U6.13 | length 275.5
  Top Layer w10: U5.5 667.95,1245.95 v1(669,1247) ; v1(783,1257) 793.46,1267.46 U6.13 U6.13@793.46,1299.68
  Bottom Layer w10: v1(669,1247) 679,1257 v1(783,1257)
RXD_S: D4.2 P2.3 U6.22 | length 1449.5
  Top Layer w10: U6.22 970.63,1269.06 1003,1236.68 1003,336.68 1183,156.68 P2.3
  Bottom Layer w10: D4.2 1167,154 1183,138 P2.3 ; D4.2@1172,156 ccw(c1188.9,156) 1176.95,144.05
RXD_USB: U5.8 U8.26 | length 198.7
  Top Layer w10: 667.95,1128.78 667.95,1098.05 771.82,994.18 U8.26
S_EN: P2.1 U6.11 | length 1663.2
  Top Layer w10: v1(686,998.68) 608.31,998.68 554,1053 554,1283.68 683.15,1412.84 U6.11
  Bottom Layer w10: v1(686,998.68) 950,734.68 950,104.68 P2.1
SCL: P3.3 R4.1 U6.42 | length 473.3
  Top Layer w10: U6.42 911.57,1816.26 935,1839.68 1010,1839.68 1034.25,1863.94 1034.25,1939.68
  Bottom Layer w10: R4.1@1028.04,1867.83 ccw(c1013.06,1882.82) 1034.25,1882.82 ccw(c1055.45,1882.82) R4.1@1040.46,1867.83 ; R4.1@1034.25,1859.43 1034.25,1939.68
SDA: P3.4 R2.1 U6.43 | length 887.4
  Top Layer w10: U6.43 891.89,1752.8 775,1869.68 775,1979.68 800,2004.68 1110,2004.68 1134.25,1980.43 1134.25,1939.68
  Bottom Layer w10: R2.1@1127.79,1867.83 ccw(c1112.2,1883.43) 1134.25,1883.43 ; R2.1@1134.25,1859.43 1134.25,1939.68 ; 1134.25,1882.21 ccw(c1154.59,1882.21) R2.1@1140.21,1867.83
SWCLK: P1.3 U6.37 | length 814.4
  Top Layer w10: U6.37 v1(1095,1674.68) v1(1095,1674.68)
  Bottom Layer w10: v1(1095,1674.68) 1823,1674.68 P1.3
SWDIO: P1.2 U6.34 | length 860.5
  Top Layer w10: U6.34 1145.63,1570.32 1165,1589.68 1165,1634.68 1280,1749.68 1655,1749.68 1681,1723.69 P1.2
TXD_G: U3.20 U6.31 | length 900.8
  Top Layer w10: v1(965,1494.68) 981.57,1511.26 U6.31 ; U3.20 1280.23,999.91 1330,1049.68 v1(1330,1139.68)
  Bottom Layer w10: v1(965,1494.68) 965,1399.68 1166,1198.68 1271,1198.68 v1(1330,1139.68)
TXD_MCU: U5.4 U6.12 | length 247.4
  Top Layer w10: U6.12 728.5,1216.5 750.94,1194.05 U5.4
TXD_S: D5.2 P2.2 U6.21 | length 1419.2
  Top Layer w10: U6.21 950.94,1239.68 972,1218.63 972,302.68 1083,191.68 P2.2
  Bottom Layer w10: D5.2 D5.2@1067,154 ; D5.2@1067,157 D5.2@1067,154 ; D5.2@1072,156 ccw(c1088.9,156) 1076.95,144.05 ; P2.2 1083,138 D5.2@1067,154
TXD_USB: U5.1 U8.25 | length 162.5
  Top Layer w10: U5.1 791.5,1133.5 U8.25
USB-VBUS: C14.1 C18.1 C19.1 R6.1 R21.2 U5.7 U7.4 U7.8 U8.7 U8.8 U9.1 U10.5 | length 3134.2
  Top Layer w10: U5.7 699.31,1154.68 761,1093 v1(761,1047.68) ; 702,802.13 U8.7 ; 710,794.13 U8.8 ; U10.5 727.69,542.37 750,564.68 v1(790,564.68) 895,564.68 911,580.68 R21.2 ; R21.2@904.79,600.48 cw(c889.8,585.49) 911,585.49 cw(c932.2,585.49) R21.2@917.21,600.48
  Top Layer w15: v1@690,781.68 706.22,797.91
  Top Layer w20: U7.8 166,578.68 195,549.68 320,549.68 338.46,531.22 R6.1 v2(338.46,429.68) 338.46,396.22 ; C18.1@333.2,357.99 ccw(c320.39,370.79) 338.5,370.79 ccw(c356.61,370.79) C18.1@343.8,357.99 ; 338.5,396.18 C18.1 338.5,339.18 393,284.68 650,284.68 710,224.68 U9.1 ; U7.4 v2(487,756.69)
  Bottom Layer w20: v2(338.46,429.68) 413,429.68 446,462.68 446,537.22 473.46,564.68 ; v1(690,774.68) 672,756.69 v2(487,756.69) ; v1(761,1047.68) 497,1047.68 446,996.68 446,797.69 v2(487,756.69) ; v1(790,564.68) 473.46,564.68 ; 473.46,564.68 446,592.15 446,715.68 v2(487,756.69)
VDD: C1.2 C4.1 C5.1 C7.1 C8.1 C13.2 C20.1 C21.1 P1.1 P2.4 P3.1 R2.2 R3.1 R4.2 R5.1 R7.2 R8.2 R12.1 R14.1 U1.5 U2.3 U2.7 U2.8 U3.23 U5.3 U5.6 U6.1 U6.9 U6.24 U6.36 U6.48 | length 3066.2
  Top Layer w10: R12.1 607.63,1174.37 U5.6 726.63,1174.37 v1(734,1167) 741.37,1174.37 U5.3 ; R12.1@612.21,1169.79 cw(c623.26,1158.74) 623.26,1174.37 ; R12.1@612.21,1182.21 ccw(c631.13,1201.13) 631.13,1174.37 ; U6.9 792.48,1452.2 815,1429.68 v1(815,1424.68) ; U6.1 795,1609.68 ; U6.48 793.46,1611.22 795,1609.68 ; v1(810,1589.68) 810,1594.68 795,1609.68 ; U6.24 1072.5,1328.19 1103,1297.68 1182,1297.68 v1(1200,1279.68) ; U6.36 1120,1609.68 1135,1624.68 v1(1135,1724.68) ; 1076.97,1323.72 ccw(c1097.88,1344.63) C20.1@1101.83,1315.32 ; C20.1@1109.21,1292.54 cw(c1121.63,1280.12) 1121.63,1297.68 ; C20.1@1109.21,1304.96 ccw(c1126.76,1322.51) 1126.76,1297.68 ; U2.8 1427.5,1484.68 1440.5,1471.68 1463.5,1471.68 1477.5,1485.69 U2.7 ; U2.8@1433.89,1489.83 ccw(c1445.47,1484.65) 1436.5,1475.69 ; 1467,1475.19 ccw(c1456.13,1486.06) U2.7@1470.82,1490.61 ; U2.3@1522.55,1267.74 cw(c1510.6,1255.79) 1527.5,1255.79 cw(c1544.4,1255.79) U2.3@1532.45,1267.74 ; v1(1527.5,1202.18) U2.3
  Top Layer w15: v1(365,1239.68) 371,1245.68 R8.2 ; R8.2@422.95,1241.24 ccw(c412.23,1230.52) 412.23,1245.68 ccw(c412.23,1260.85) R8.2@422.95,1250.13 ; v1(1060,374.68) 1089,345.68 R5.1 ; C5.1@1144.5,1060.24 cw(c1130.47,1046.22) 1150.31,1046.22 ; C5.1@1144.5,1069.13 ccw(c1130.47,1083.15) 1150.31,1083.15 ; U3.23 1150.31,1119.99 v1(1185,1154.68) ; R5.1@1169.56,341.24 ccw(c1158.84,330.52) 1158.84,345.68 ccw(c1158.84,360.85) R5.1@1169.56,350.13 ; C4.1@1177.5,1154.68 cw(c1159.39,1154.68) 1172.2,1141.88 cw(c1185,1129.08) C4.1@1185,1147.18 ; v1(1342.5,1530.68) U2.8 ; C7.1@1346.94,1526.24 cw(c1357.66,1515.52) 1357.66,1530.68 cw(c1357.66,1545.85) C7.1@1346.94,1535.13 ; C7.1@1347.81,1525.38 cw(c1360.61,1512.58) 1360.61,1530.68 cw(c1360.61,1548.79) C7.1@1347.81,1535.99 ; v1@1760,1427.18 cw(c1760,1409.08) 1772.8,1421.88 cw(c1785.61,1434.68) v1@1767.5,1434.68 ; v1(1760,1434.68) 1802,1392.68 R14.1 ; v1(1775,784.68) 1775,775.68 R3.1 ; R14.1@1814.56,1388.24 ccw(c1803.84,1377.52) 1803.84,1392.68 ccw(c1803.84,1407.85) R14.1@1814.56,1397.13
  Top Layer w20: P2.4 1283,172.68 1363,252.68 R7.2
  Top Layer w25: U1.5 610.18,1983 C1.2 634.5,1974.18 686,1922.68 686,1844 ; 591.68,1983 cw(c591.68,1949.37) C1.2@615.46,1973.15 ; C1.2@619,1966.68 cw(c619,1911.16) 658.26,1950.42
  Bottom Layer w15: C13.2@834,1858.69 C13.2@834.25,1858.94 ; R4.2 R2.2 ; R4.2@1038.69,1802.06 cw(c1049.41,1791.34) 1049.41,1806.5 cw(c1049.41,1821.66) R4.2@1038.69,1810.94 ; v1@1079.7,1801.2 ccw(c1066.89,1788.4) 1066.89,1806.5 ccw(c1066.89,1824.61) v1@1079.7,1811.81 ; v1@1090.3,1801.2 cw(c1103.11,1788.4) 1103.11,1806.5 cw(c1103.11,1824.61) v1@1090.3,1811.81 ; R2.2@1129.56,1802.06 ccw(c1118.84,1791.34) 1118.84,1806.5 ccw(c1118.84,1821.66) R2.2@1129.56,1810.94
  Bottom Layer w20: C13.2 834.25,1849.25 834.25,1939.68
  other v1: 1200,1111.68 1234,1138.68 848,1201 694,1799.68 1085,1806.5 654,1839.68 734,1839.68
pads on no net: S1.0 S3.0 S6.0 U3.1 U3.2 U3.4 U3.5 U3.6 U3.14 U3.15 U3.16 U3.17 U3.18 U3.19 U6.2 U6.3 U6.4 U6.10 U6.14 U6.15 U6.16 U6.17 U6.18 U6.19 U6.38 U6.39 U6.40 U6.41 U6.45 U6.46 U7.0 U8.1 U8.2 U8.10 U8.12 U8.13 U8.14 U8.15 U8.16 U8.17 U8.18 U8.19 U8.20 U8.21 U8.22 U8.23 U8.24 U8.27 U8.28 U9.4

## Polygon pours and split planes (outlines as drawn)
GND on Bottom Layer "Top Layer-No Net" (solid, remove dead copper, pour order 1000): 103,2139.68 100,2139.68 ccw(c100,2039.68) 0,2039.68 0,2005.68 0,100 ccw(c100,100) 100,0 1857,0 1868.5,0 ccw(c1868.5,100) 1968.5,100 1968.5,1972.68 1968.5,2039.68 ccw(c1868.5,2039.68) 1868.5,2139.68 1686,2139.68
GND on Top Layer "Top Layer-No Net" (solid, remove dead copper, pour order 1001): 103,2139.68 100,2139.68 ccw(c100,2039.68) 0,2039.68 0,2005.68 0,100 ccw(c100,100) 100,0 1857,0 1868.5,0 ccw(c1868.5,100) 1968.5,100 1968.5,1972.68 1968.5,2039.68 ccw(c1868.5,2039.68) 1868.5,2139.68 1686,2139.68
GND on GND (split plane): 1885.36,2119.33 1892.16,2118.32 1898.82,2116.66 1905.29,2114.34 1911.49,2111.41 1917.39,2107.87 1922.9,2103.78 1927.99,2099.17 1932.6,2094.08 1936.69,2088.57 1940.22,2082.68 1943.16,2076.47 1945.47,2070 1947.14,2063.34 1948.15,2056.54 1948.46,2050.23 1948.41,2049.68 1948.41,90 1948.46,89.45 1948.15,83.14 1947.14,76.35 1945.47,69.68 1943.16,63.22 1940.22,57.01 1936.69,51.12 1932.6,45.6 1927.99,40.51 1922.9,35.9 1917.39,31.81 1911.49,28.28 1905.29,25.34 1898.82,23.03 1892.16,21.36 1885.36,20.35 1879.05,20.04 1878.5,20.1 90,20.1 89.45,20.04 83.14,20.35 76.35,21.36 69.68,23.03 63.22,25.34 57.01,28.28 51.12,31.81 45.6,35.9 40.51,40.51 35.9,45.6 31.81,51.12 28.28,57.01 25.34,63.22 23.03,69.68 21.36,76.35 20.35,83.14 20.04,89.45 20.1,90 20.1,2049.68 20.04,2050.23 20.35,2056.54 21.36,2063.34 23.03,2070 25.34,2076.47 28.28,2082.68 31.81,2088.57 35.9,2094.08 40.51,2099.17 45.6,2103.78 51.12,2107.87 57.01,2111.41 63.22,2114.34 69.68,2116.66 76.35,2118.32 83.14,2119.33 89.45,2119.64 90,2119.59 1878.5,2119.59 1879.05,2119.64
VDD on VDD (split plane): 1884.1,2099.35 1889.63,2098.41 1895.01,2096.86 1900.19,2094.71 1905.09,2092 1909.66,2088.76 1913.84,2085.03 1917.58,2080.85 1920.82,2076.28 1923.53,2071.37 1925.68,2066.19 1927.23,2060.81 1928.17,2055.28 1928.45,2050.21 1928.42,2049.68 1928.42,90 1928.45,89.47 1928.17,84.4 1927.23,78.88 1925.68,73.49 1923.53,68.32 1920.82,63.41 1917.58,58.84 1913.84,54.66 1909.66,50.93 1905.09,47.68 1900.19,44.97 1895.01,42.83 1889.63,41.27 1884.1,40.34 1879.03,40.05 1878.5,40.09 915,40.09 915,899.68 40.09,899.68 40.09,2049.68 40.05,2050.21 40.34,2055.28 41.27,2060.81 42.83,2066.19 44.97,2071.37 47.68,2076.28 50.93,2080.85 54.66,2085.03 58.84,2088.76 63.41,2092 68.32,2094.71 73.49,2096.86 78.88,2098.41 84.4,2099.35 89.47,2099.63 90,2099.6 1878.5,2099.6 1879.03,2099.63

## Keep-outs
Keep-Out Layer:
  circle w10: c196.85,1937.01 r59.06
  circle w10: c1771.65,1937.01 r59.06
  circle w10: c196.85,216.54 r59.06
  lines w8: 0,90 ccw(c90,90) 90,0 1878.5,0 ccw(c1878.5,90) 1968.5,90 1968.5,2049.68 ccw(c1878.5,2049.68) 1878.5,2139.68 90,2139.68 ccw(c90,2049.68) 0,2049.68 0,90

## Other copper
Top Layer:
  rectangle net VDD: 1169,1092.68 1252,1172.68
  rectangle net VDD: 639,1784.68 749,1854.68
VDD (plane layer: these items are gaps in the copper):
  rectangle: 10,4.68 915,899.68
